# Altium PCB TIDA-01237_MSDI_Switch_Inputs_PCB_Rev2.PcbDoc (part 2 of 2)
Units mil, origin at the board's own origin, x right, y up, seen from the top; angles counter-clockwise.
Board outline 3000 x 5250 mil, 2 copper layers (Top Layer, Bottom Layer), stack 62 mil thick; 161 components, 119 nets, 511 pads, 360 vias.
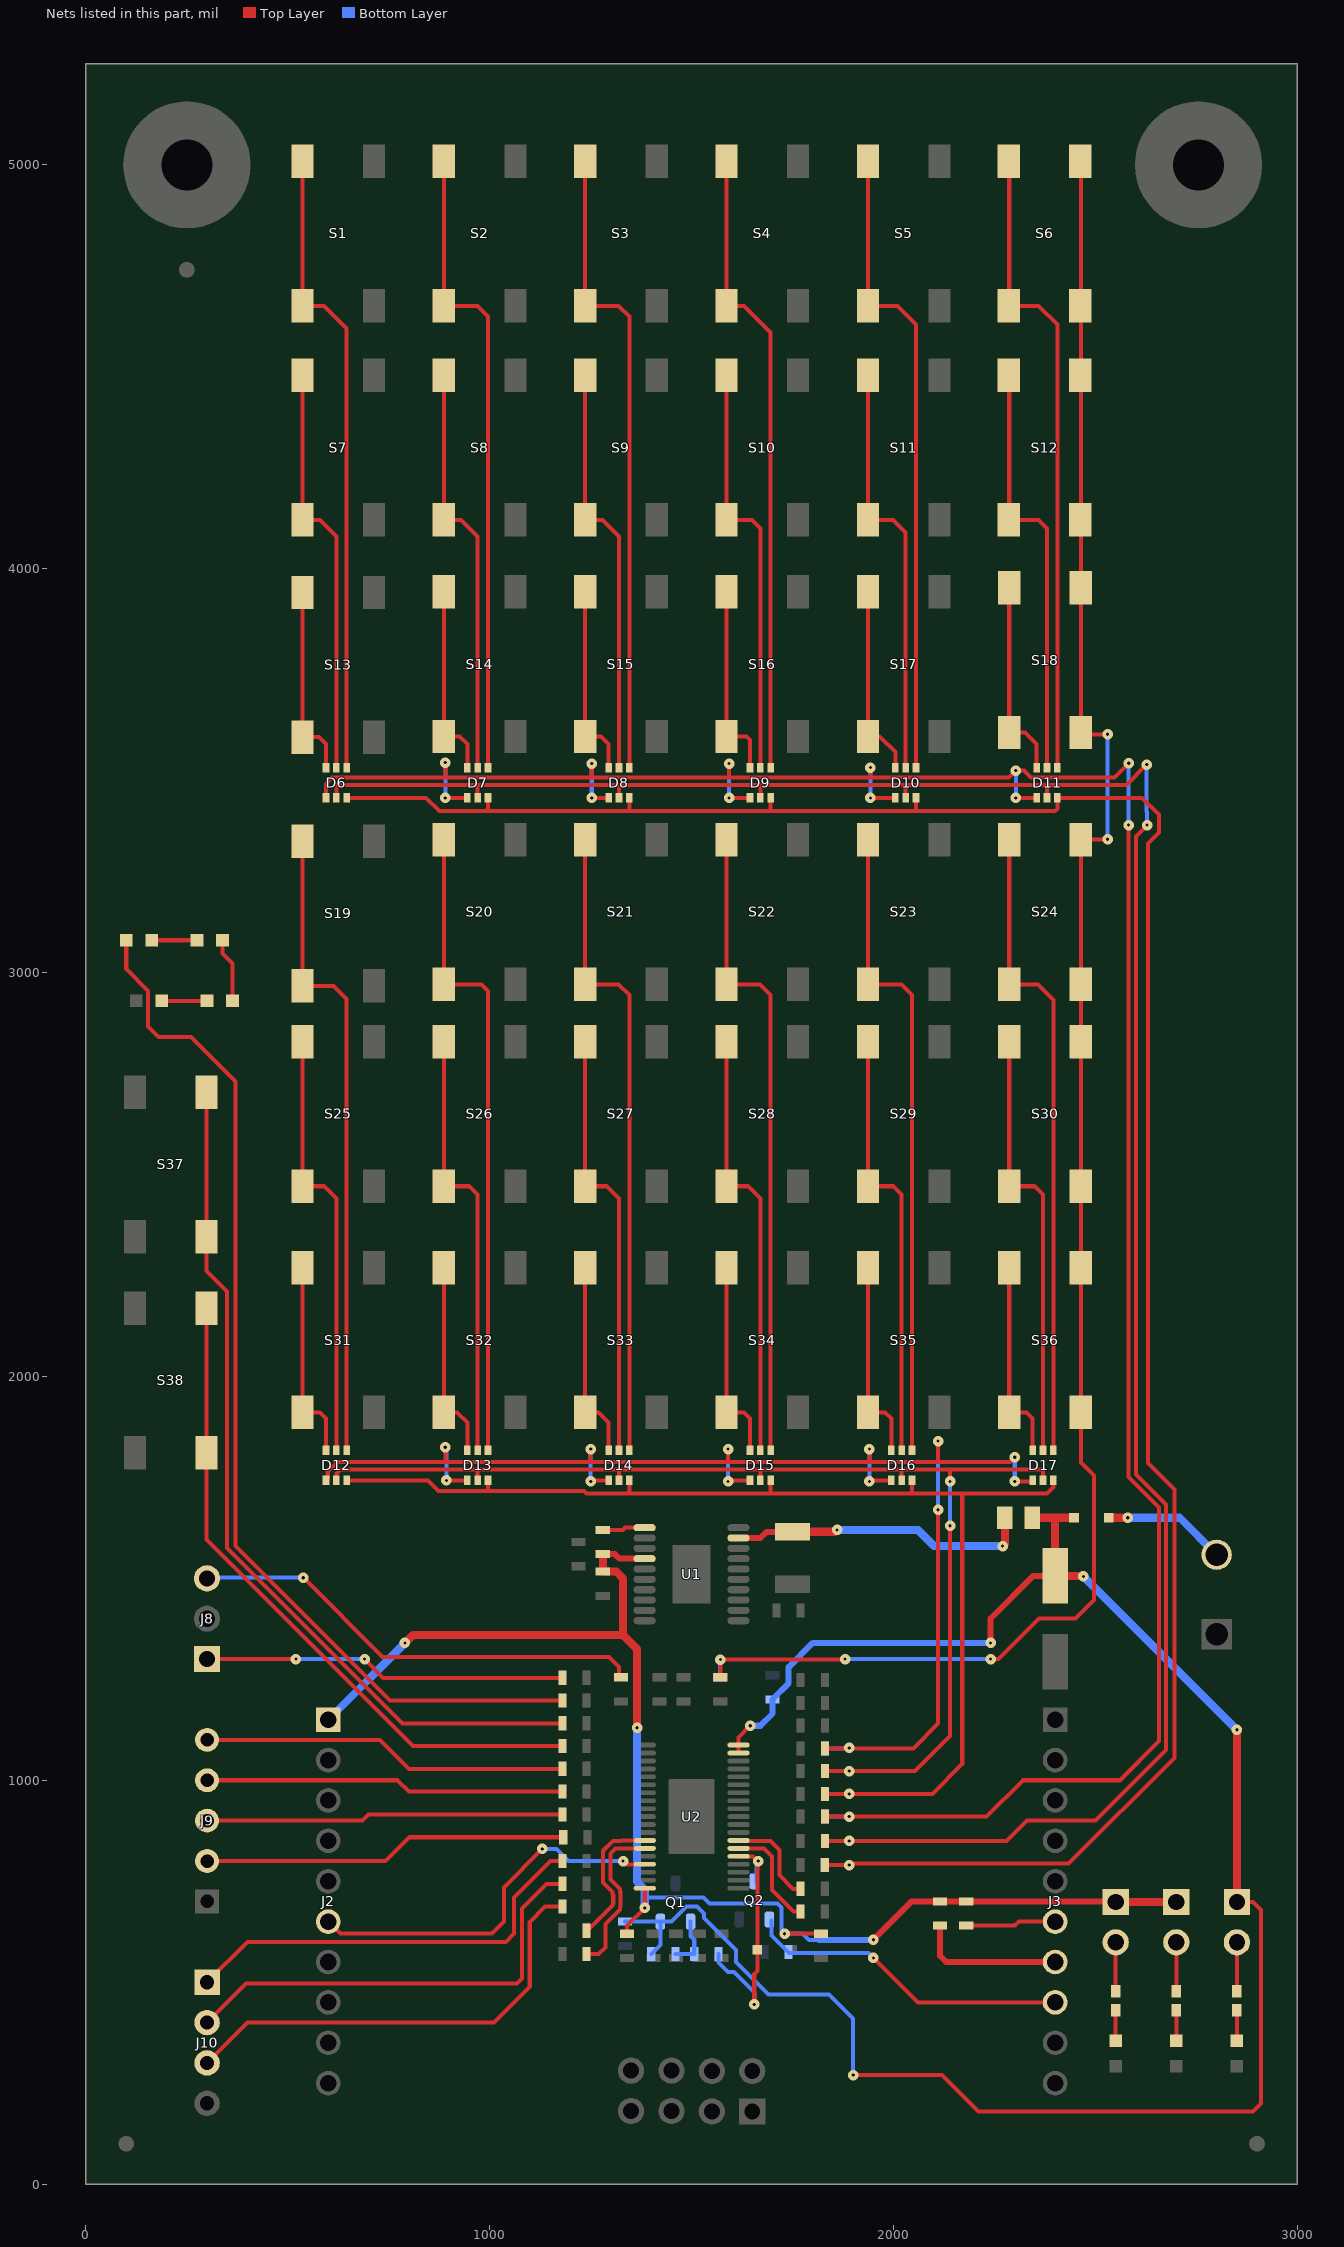
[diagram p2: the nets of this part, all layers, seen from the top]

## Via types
v1: diameter 20, hole 10, Top Layer to Bottom Layer, tented both sides, 214 vias
v2: diameter 26, hole 7.87, Top Layer to Bottom Layer, tented both sides, 116 vias
v3: diameter 19.68, hole 7.87, Top Layer to Bottom Layer, tented both sides, 18 vias
v4: diameter 26, hole 7.87, Top Layer to Bottom Layer, 12 vias

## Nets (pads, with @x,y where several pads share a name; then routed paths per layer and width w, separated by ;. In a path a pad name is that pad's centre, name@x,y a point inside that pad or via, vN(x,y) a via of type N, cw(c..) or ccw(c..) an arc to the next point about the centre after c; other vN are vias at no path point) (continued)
NetC21_1: C21.1 R22.1 S6.1 S6.2 S12.1 S12.2 S18.1 S18.2 S24.1 S24.2 S30.1 S30.2 S36.1 S36.2 | length 4778.2
  Top Layer w10: R22.1@1571.23,1255 v2(1571.23,1298.77) 1878.77,1298.77 v2(1880,1300) ; v2(2240,1300) 2260,1300 2360,1400 2450,1400 2495.87,1445.87 2495.87,1754.13 2463.58,1786.42 S36.2@2463.58,1910.87 S36.1@2463.58,2269.13 S30.2@2463.58,2470.87 S30.1@2463.58,2829.13 S24.2@2463.58,2970.87 S24.1@2463.58,3329.13 2529.13,3329.13 v2(2530,3330) ; S6.1@2463.58,5009.13 2463.58,4650.87 2463.58,4479.13 2463.58,4120.87 S18.1@2463.58,3952.8 S18.2@2463.58,3594.53 2468.11,3590 v2(2530,3590)
  Bottom Layer w10: C21.1@1570,1255 v2@1570,1297.54 ; v2(1880,1300) v2(2240,1300) ; v2(2530,3330) v2(2530,3590)
NetD2_2: D2.2 R3.1 | length 75.2
  Top Layer w10: D2.2@2550,354.96 R3.1@2550,430.18
NetD3_2: D3.2 R4.1 | length 75.2
  Top Layer w10: D3.2@2700,354.96 R4.1@2700,430.18
NetD4_2: D4.2 R5.1 | length 75.2
  Top Layer w10: D4.2@2850,354.96 R5.1@2850,430.18
NetD5_1: D5.1 Q2.3 R12.2 U2.24 | length 639.6
  Top Layer w10: U2.24@1616.14,811.58 1651.97,811.58 1662.47,801.07 D5.1@1662.47,580 1662.47,527.53 1655,520.05 v2(1655,445) ; v4@1663.54,800 v4(1665,800)
  Bottom Layer w10: R12.2@1566.45,570 1566.45,548.55 1590,525 1605,525 1655,475 v2(1655,445) ; Q2.3@1660,747.24 1660,798.59 1662.47,801.07 1663.54,800 v4(1665,800)
NetD6_1: D6.1 S1.3 S1.4 | length 1577.8
  Top Layer w10: S1.3@536.42,5009.13 S1.4@536.42,4650.87 589.13,4650.87 645.59,4594.41 D6.1@645.59,3507.4
NetD6_2: D6.2 S7.3 S7.4 | length 1031.4
  Top Layer w10: S7.3@536.42,4479.13 S7.4@536.42,4120.87 579.13,4120.87 620,4080 D6.2@620,3507.4
NetD6_3: D6.3 S13.3 S13.4 | length 481.6
  Top Layer w10: S13.3@536.42,3941.02 S13.4@536.42,3582.76 577.24,3582.76 594.41,3565.59 D6.3@594.41,3507.4
NetD7_1: D7.1 S2.3 S2.4 | length 1595.4
  Top Layer w10: S2.3@886.42,5009.13 S2.4@886.42,4650.87 969.13,4650.87 995.59,4624.41 D7.1@995.59,3507.4
NetD7_2: D7.2 S8.3 S8.4 | length 1031.4
  Top Layer w10: S8.3@886.42,4479.13 S8.4@886.42,4120.87 929.13,4120.87 970,4080 D7.2@970,3507.4
NetD7_3: D7.3 S14.3 S14.4 | length 482.3
  Top Layer w10: S14.3@886.42,3942.8 S14.4@886.42,3584.53 925.47,3584.53 944.41,3565.59 D7.3@944.41,3507.4
NetD8_1: D8.1 S3.3 S3.4 | length 1595.4
  Top Layer w10: S3.3@1236.42,5009.13 S3.4@1236.42,4650.87 1319.13,4650.87 1345.59,4624.41 D8.1@1345.59,3507.4
NetD8_2: D8.2 S9.3 S9.4 | length 1031.4
  Top Layer w10: S9.3@1236.42,4479.13 S9.4@1236.42,4120.87 1279.13,4120.87 1320,4080 D8.2@1320,3507.4
NetD8_3: D8.3 S15.3 S15.4 | length 482.3
  Top Layer w10: S15.3@1236.42,3942.8 S15.4@1236.42,3584.53 1275.47,3584.53 1294.41,3565.59 D8.3@1294.41,3507.4
NetD9_1: D9.1 S4.3 S4.4 | length 1572
  Top Layer w10: S4.3@1586.42,5009.13 S4.4@1586.42,4650.87 1629.13,4650.87 1695.59,4584.41 D9.1@1695.59,3507.4
NetD9_2: D9.2 S10.3 S10.4 | length 1043.1
  Top Layer w10: S10.3@1586.42,4479.13 S10.4@1586.42,4120.87 1649.13,4120.87 1670,4100 D9.2@1670,3507.4
NetD9_3: D9.3 S16.3 S16.4 | length 488.2
  Top Layer w10: S16.3@1586.42,3942.8 S16.4@1586.42,3584.53 1635.47,3584.53 1644.41,3575.59 D9.3@1644.41,3507.4
NetD10_1: D10.1 S5.3 S5.4 | length 1593.7
  Top Layer w10: S5.3@1936.42,5009.13 S5.4@1936.42,4650.87 2009.13,4650.87 2055.59,4604.41 D10.1@2055.59,3507.4
NetD10_2: D10.2 S11.3 S11.4 | length 1047.2
  Top Layer w10: S11.3@1936.42,4479.13 S11.4@1936.42,4120.87 1999.13,4120.87 2030,4090 D10.2@2030,3507.4
NetD10_3: D10.3 S17.3 S17.4 | length 480.6
  Top Layer w10: S17.3@1936.42,3942.8 S17.4@1936.42,3584.53 1965.47,3584.53 2004.41,3545.59 D10.3@2004.41,3507.4
NetD11_1: D11.1 S6.3 S6.4 | length 1593.7
  Top Layer w10: S6.3@2286.42,5009.13 2286.42,4650.87 2359.13,4650.87 2405.59,4604.41 D11.1@2405.59,3507.4
NetD11_2: D11.2 S12.3 S12.4 | length 1053.1
  Top Layer w10: S12.3@2286.42,4479.13 2286.42,4120.87 2359.13,4120.87 2380,4100 D11.2@2380,3507.4
NetD11_3: D11.3 S18.3 S18.4 | length 496.4
  Top Layer w10: S18.3@2286.42,3952.8 S18.4@2286.42,3594.53 2325.47,3594.53 2354.41,3565.59 D11.3@2354.41,3507.4
NetD12_1: D12.1 S19.3 S19.4 | length 1598
  Top Layer w10: S19.3@536.42,3325.47 S19.4@536.42,2967.2 612.8,2967.2 645.59,2934.41 D12.1@645.59,1817.4
NetD12_2: D12.2 S25.3 S25.4 | length 1077.2
  Top Layer w10: S25.3@536.42,2829.13 S25.4@536.42,2470.87 589.13,2470.87 620,2440 D12.2@620,1817.4
NetD12_3: D12.3 S31.3 S31.4 | length 500.8
  Top Layer w10: S31.3@536.42,2269.13 S31.4@536.42,1910.87 579.13,1910.87 594.41,1895.59 D12.3@594.41,1817.4
NetD13_1: D13.1 S20.3 S20.4 | length 1611.3
  Top Layer w10: S20.3@886.42,3329.13 S20.4@886.42,2970.87 979.13,2970.87 995.59,2954.41 D13.1@995.59,1817.4
NetD13_2: D13.2 S26.3 S26.4 | length 1083.1
  Top Layer w10: S26.3@886.42,2829.13 S26.4@886.42,2470.87 949.13,2470.87 970,2450 D13.2@970,1817.4
NetD13_3: D13.3 S32.3 S32.4 | length 494.9
  Top Layer w10: S32.3@886.42,2269.13 S32.4@886.42,1910.87 919.13,1910.87 944.41,1885.59 D13.3@944.41,1817.4
NetD14_1: D14.1 S21.3 S21.4 | length 1605.4
  Top Layer w10: S21.3@1236.42,3329.13 S21.4@1236.42,2970.87 1319.13,2970.87 1345.59,2944.41 D14.1@1345.59,1817.4
NetD14_2: D14.2 S27.3 S27.4 | length 1077.2
  Top Layer w10: S27.3@1236.42,2829.13 S27.4@1236.42,2470.87 1289.13,2470.87 1320,2440 D14.2@1320,1817.4
NetD14_3: D14.3 S33.3 S33.4 | length 494.9
  Top Layer w10: S33.3@1236.42,2269.13 S33.4@1236.42,1910.87 1269.13,1910.87 1294.41,1885.59 D14.3@1294.41,1817.4
NetD15_1: D15.1 S22.3 S22.4 | length 1605.4
  Top Layer w10: S22.3@1586.42,3329.13 S22.4@1586.42,2970.87 1669.13,2970.87 1695.59,2944.41 D15.1@1695.59,1817.4
NetD15_2: D15.2 S28.3 S28.4 | length 1077.2
  Top Layer w10: S28.3@1586.42,2829.13 S28.4@1586.42,2470.87 1639.13,2470.87 1670,2440 D15.2@1670,1817.4
NetD15_3: D15.3 S34.3 S34.4 | length 500.8
  Top Layer w10: S34.3@1586.42,2269.13 S34.4@1586.42,1910.87 1629.13,1910.87 1644.41,1895.59 D15.3@1644.41,1817.4
NetD16_1: D16.1 S23.3 S23.4 | length 1605.4
  Top Layer w10: S23.3@1936.42,3329.13 S23.4@1936.42,2970.87 2019.13,2970.87 2045.59,2944.41 D16.1@2045.59,1817.4
NetD16_2: D16.2 S29.3 S29.4 | length 1083.1
  Top Layer w10: S29.3@1936.42,2829.13 S29.4@1936.42,2470.87 1999.13,2470.87 2020,2450 D16.2@2020,1817.4
NetD16_3: D16.3 S35.3 S35.4 | length 500.8
  Top Layer w10: S35.3@1936.42,2269.13 S35.4@1936.42,1910.87 1979.13,1910.87 1994.41,1895.59 D16.3@1994.41,1817.4
NetD17_1: D17.1 S24.3 S24.4 | length 1598.5
  Top Layer w10: S24.3@2286.42,3329.13 S24.4@2286.42,2970.87 2357.3,2970.87 2395.59,2932.57 D17.1@2395.59,1817.4
NetD17_2: D17.2 S30.3 S30.4 | length 1083.1
  Top Layer w10: S30.3@2286.42,2829.13 S30.4@2286.42,2470.87 2349.13,2470.87 2370,2450 D17.2@2370,1817.4
NetD17_3: D17.3 S36.3 S36.4 | length 500.8
  Top Layer w10: S36.3@2286.42,2269.13 S36.4@2286.42,1910.87 2329.13,1910.87 2344.41,1895.59 D17.3@2344.41,1817.4
NetD18_1: D18.1 D19.2 | length 112
  Top Layer w10: D18.1@163.03,3080 D19.2@275.04,3080
NetD18_2: D18.2 R32.1 | length 2627.2
  Top Layer w10: D18.2@100.04,3080 D18.2@100.04,3080 100,3008.4 153.66,2954.74 153.66,2866.34 180,2840 260,2840 370,2730 370,1580 752.62,1197.38 R32.1@1180,1197.38
NetD19_1: D19.1 D20.2 | length 160.4
  Top Layer w10: D19.1@338.03,3080 338.03,3047.13 363.03,3022.13 D20.2@363.03,2930
NetD20_1: D20.1 D21.2 | length 112
  Top Layer w10: D21.2@188.03,2930 D20.1@300.04,2930
NetJ4_2: J4.2 R3.2 | length 121.4
  Top Layer w10: R3.2@2550,477.42 J4.2@2550,598.81
NetJ5_2: J5.2 R4.2 | length 121.4
  Top Layer w10: R4.2@2700,477.42 J5.2@2700,598.81
NetJ6_2: J6.2 R5.2 | length 121.4
  Top Layer w10: R5.2@2850,477.42 J6.2@2850,598.81
NetJ8_1: J8.1 R29.1 | length 899.2
  Top Layer w10: J8.1@300,1300 v2(520,1300) ; v2(690,1300) 736.31,1253.69 R29.1@1180,1253.69
  Bottom Layer w10: v2(520,1300) v2(690,1300)
NetJ8_3: J8.3 R28.1 | length 1137.4
  Top Layer w10: v2(538.42,1501.58) 735,1305 1295,1305 1320,1280 R28.1@1320,1255
  Bottom Layer w10: J8.3@300,1500 301.58,1501.58 v2(538.42,1501.58)
NetJ9_2: J9.2 R36.1 | length 906.4
  Top Layer w10: J9.2@300,800 742.15,800 801.07,858.93 R36.1@1181.95,858.93
NetJ9_3: J9.3 R35.1 | length 886.3
  Top Layer w10: J9.3@300,900 685,900 700.24,915.24 R35.1@1180,915.24
NetJ9_4: J9.4 R34.1 | length 891.5
  Top Layer w10: J9.4@300,1000 772.15,1000 800,972.15 R34.1@1180,972.15
NetJ9_5: J9.5 R33.1 | length 909.6
  Top Layer w10: J9.5@300,1100 728.46,1100 800,1028.46 R33.1@1180,1028.46
NetJ10_1: J10.1 R39.1 | length 1057
  Top Layer w10: J10.1@300,500 400,600 1040,600 1060,620 1060,710 1150,800 R39.1@1180,800
NetJ10_2: J10.2 R38.1 | length 1124
  Top Layer w10: J10.2@300,400 397.06,497.06 1067.78,497.06 1080,509.28 1080,682.8 1140.89,743.69 R38.1@1180,743.69
NetJ10_3: J10.3 R37.1 | length 1134.2
  Top Layer w10: J10.3@300,300 400,400 1010,400 1099.13,489.13 1099.13,649.13 1137.38,687.38 R37.1@1180,687.38
NetQ1_1: Q1.1 R10.1 R12.1 | length 130.4
  Bottom Layer w10: R10.1@1460,570 R12.1@1506.45,570 1506.45,604.72 1497.4,613.77 Q1.1@1497.4,650.21
NetR2_1: R2.1 U1.1 | length 105.8
  Top Layer w10: R2.1@1280,1620 1330,1620 1335.47,1625.47 U1.1@1383.54,1625.47
NetR8_2: R8.2 U2.13 | length 350.4
  Top Layer w10: R8.2@1240,627.38 1241.63,627.38 1304.25,690 1304.25,692.66 1305.87,694.28 1305.87,715.72 1304.25,717.34 1304.25,723.88 1280.75,747.38 1280.75,825.47 1305.28,850 1325.97,850 1326.91,850.95 U2.13@1383.86,850.95
NetR9_2: R9.2 U2.14 | length 401.6
  Top Layer w10: R9.2@1240,569.69 1269.69,569.69 1286.25,586.25 1286.25,644.13 1322.13,680 1322.13,682.6 1322.13,685.26 1323.75,686.88 1323.75,723.12 1322.13,724.74 1322.13,731.28 1298.62,754.79 1298.62,818.07 1311.82,831.26 U2.14@1383.86,831.26
NetR11_2: R11.2 U2.25 | length 266.8
  Top Layer w10: U2.25@1616.14,831.26 1678.74,831.26 1699.25,810.75 1699.25,728.42 1752.68,674.99 R11.2@1770,674.99
NetR14_2: R14.2 U2.26 | length 239.9
  Top Layer w10: U2.26@1616.14,850.95 1617.05,850.04 1694.96,850.04 1717.13,827.87 1717.13,765.6 1751.42,731.3 R14.2@1770,731.3
NetR30_1: R30.1 S37.1 S37.2 | length 2160.2
  Top Layer w10: S37.1@298.58,2704.03 S37.2@298.58,2345.76 298.58,2261.42 350,2210 350,1574.72 745.21,1179.51 745.49,1179.51 783.93,1141.07 1178.5,1141.07 R30.1@1180,1141.07
NetR31_1: R31.1 S38.1 S38.2 | length 1666.1
  Top Layer w10: S38.1@298.58,2169.13 S38.2@298.58,1810.87 298.58,1596.42 810.24,1084.76 1178.5,1084.76 R31.1@1180,1084.76
P1_6: J3.7 R41.1 | length 364.7
  Top Layer w15: R41.1@2115,638.5 2115,565 2130,550 J3.7@2400,550
P1_7: J3.6 R40.1 | length 224.1
  Top Layer w10: R40.1@2180,640 2300,640 2310,650 J3.6@2400,650
R1: C15.1 D6.6 D7.6 D8.6 D9.6 D10.6 D11.6 R16.1 | length 5619.5
  Top Layer w10: D6.6@645.59,3432.6 842.4,3432.6 875,3400 990,3400 ; D7.6@995.59,3432.6 995.59,3405.59 990,3400 ; D8.6@1345.59,3432.6 1345.59,3405.59 1340,3400 ; D9.6@1695.59,3432.6 1695.59,3405.59 1690,3400 ; R16.1@1830,790 v2(1890,790) 1893.39,793.39 2433.39,793.39 2695,1055 2695,1720 2630,1785 2630,3320 2656.67,3346.67 2656.67,3390.92 2615,3432.6 D11.6@2405.59,3432.6 2405.59,3405.59 2400,3400 2050,3400 ; D10.6@2055.59,3432.6 2055.59,3405.59 2050,3400 ; 990,3400 1340,3400 ; 1340,3400 1690,3400 ; 1690,3400 2050,3400
  Bottom Layer w10: C15.1@1830,790 v2(1890,790)
R2: C22.1 D6.5 D7.5 D8.5 D9.5 D10.5 D11.5 R23.1 | length 5701.4
  Top Layer w10: D6.5@620,3432.6 620,3460 624.84,3464.84 970,3464.84 ; D7.5@970,3432.6 970,3464.84 ; D8.5@1320,3432.6 1320,3464.84 ; D9.5@1670,3432.6 1670,3464.84 ; R23.1@1830,850 2280,850 2330,900 2500,900 2675,1075 2675,1682.4 2600,1757.4 2600,3336.59 2627.85,3364.43 v4(2627.85,3365) ; D10.5@2030,3432.6 2030,3464.84 ; D11.5@2380,3432.6 2380,3460 2375.16,3464.84 ; v4(2626.72,3515) 2576.56,3464.84 2375.16,3464.84 ; 970,3464.84 1320,3464.84 ; 1320,3464.84 1670,3464.84 ; 1670,3464.84 2030,3464.84 ; 2030,3464.84 2375.16,3464.84
  Bottom Layer w10: C22.1@1830,850 v2(1890,850) ; v4(2626.72,3515) 2626.72,3398.28 2627.85,3397.15 v4(2627.85,3365)
R3: C23.1 D6.4 D7.4 D8.4 D9.4 D10.4 D11.4 R24.1 | length 6270.3
  Top Layer w10: D6.4@594.41,3432.6 594.41,3467.13 610,3482.72 890,3482.72 ; v2(890,3432.6) D7.4@944.41,3432.6 ; v2(890,3520) 890,3482.72 ; v2(1252.6,3432.6) D8.4@1294.41,3432.6 ; v2(1252.6,3517.4) 1252.6,3485.31 1250,3482.72 ; v2(1592.6,3432.6) D9.4@1644.41,3432.6 ; v2(1592.6,3517.4) 1592.6,3485.31 1590,3482.72 ; R24.1@1830,910 2230,910 2320,1000 2560,1000 2657.13,1097.13 2657.13,1675 2581.72,1750.41 v4(2581.72,3365) ; v2(1942.6,3432.6) D10.4@2004.41,3432.6 ; v2(1942.6,3507.4) 1942.6,3485.31 1940,3482.72 ; v2(2302.6,3432.6) D11.4@2354.41,3432.6 ; v4(2582.13,3518.18) 2546.67,3482.72 2340.81,3482.72 2323.53,3500 v2(2302.6,3500) 2285.32,3482.72 1940,3482.72 ; 890,3482.72 1250,3482.72 ; 1250,3482.72 1590,3482.72 ; 1590,3482.72 1940,3482.72
  Bottom Layer w10: v2(890,3432.6) v2(890,3520) ; v2(1252.6,3432.6) v2(1252.6,3517.4) ; v2(1592.6,3432.6) v2(1592.6,3517.4) ; C23.1@1830,910 v2(1890,910) ; v2(1942.6,3432.6) v2(1942.6,3507.4) ; v2(2302.6,3432.6) v2(2302.6,3500) ; v4(2581.72,3365) 2581.72,3481.72 2582.13,3482.13 v4(2582.13,3518.18)
R4: C24.1 D12.6 D13.6 D14.6 D15.6 D16.6 D17.6 R25.1 | length 3044
  Top Layer w10: D12.6@645.59,1742.6 847.4,1742.6 873.28,1716.72 995.59,1716.72 ; D13.6@995.59,1742.6 995.59,1716.72 ; D14.6@1345.59,1742.6 1345.59,1715.59 1340,1710 ; D15.6@1695.59,1738.19 1695.59,1710 ; D15.6@1695.59,1742.6 1695.59,1710 ; R25.1@1830,966.31 v2(1890,966.31) 2096.31,966.31 2170,1040 2170,1710 ; D16.6@2045.59,1742.6 2045.59,1715.59 2040,1710 ; D17.6@2395.59,1742.6 2395.59,1725.59 2380,1710 2170,1710 ; 995.59,1716.72 1233.28,1716.72 1240,1710 1340,1710 ; 1340,1710 1695.59,1710 ; 1695.59,1710 2040,1710 ; 2040,1710 2170,1710
  Bottom Layer w10: C24.1@1830,966.31 v2(1890,966.31)
R5: C25.1 D12.5 D13.5 D14.5 D15.5 D16.5 D17.5 R26.1 | length 2972.9
  Top Layer w10: D12.5@620,1742.6 620,1760 630,1770 970,1770 ; D13.5@970,1742.6 970,1770 ; D14.5@1320,1742.6 1320,1770 ; D15.5@1670,1742.6 1670,1770 ; R26.1@1830,1022.62 v2(1890,1022.62) 2052.62,1022.62 2140,1110 v2(2140,1630) ; D16.5@2020,1742.6 2020,1767.5 2017.5,1770 ; v2(2140,1740) 2140,1770 ; D17.5@2370,1742.6 2370,1765 2365,1770 2140,1770 ; 970,1770 1320,1770 ; 1320,1770 1670,1770 ; 1670,1770 2017.5,1770 ; 2017.5,1770 2140,1770
  Bottom Layer w10: C25.1@1830,1022.62 v2(1890,1022.62) ; v2(2140,1630) v2(2140,1740)
R6: C26.1 D12.4 D13.4 D14.4 D15.4 D16.4 D17.4 R27.1 | length 3629.1
  Top Layer w10: D12.4@594.41,1742.6 598.86,1747.05 598.86,1764.14 622.6,1787.87 890,1787.87 ; v2(890,1824.8) 890,1787.87 ; v2(892.6,1742.6) D13.4@944.41,1742.6 ; v2(1250,1740) 1252.6,1742.6 D14.4@1294.41,1742.6 ; v2(1250,1820) 1250,1787.87 ; v2(1590,1740) 1592.6,1742.6 D15.4@1644.41,1742.6 ; v2(1590,1820) 1590,1787.87 ; R27.1@1830,1078.93 2048.93,1078.93 2110,1140 v2(2110,1670) ; v2(1940,1740) 1942.6,1742.6 D16.4@1994.41,1742.6 ; v2(1940,1820) 1940,1787.87 ; v2(2110,1840) 2110,1787.87 ; v2(2300,1740) D17.4@2341.81,1740 ; v2(2300,1800) 2287.87,1787.87 2110,1787.87 ; 890,1787.87 1250,1787.87 ; 1250,1787.87 1590,1787.87 ; 1590,1787.87 1940,1787.87 ; 1940,1787.87 2110,1787.87
  Bottom Layer w10: v2(890,1824.8) 892.6,1827.4 v2(892.6,1742.6) ; v2(1250,1740) v2(1250,1820) ; v2(1590,1740) v2(1590,1820) ; C26.1@1830,1078.93 1888.93,1078.93 v2(1890,1080) ; v2(1940,1740) v2(1940,1820) ; v2(2110,1670) v2(2110,1840) ; v2(2300,1740) v2(2300,1800)
SCLK: J2.6 U2.16 | length 937.4
  Top Layer w10: J2.6@600,650 630,620 1005,620 1035,650 1035,735 v2(1130,830) ; v2@1338.11,791.89 U2.16@1383.86,791.89
  Bottom Layer w10: v2(1130,830) 1165.17,830 1195.17,800 v2(1330,800)
UC_LDO_EN: J3.8 Q2.1 R15.1 | length 808.1
  Top Layer w10: v2(1950,560) 2060,450 J3.8@2400,450
  Bottom Layer w10: Q2.1@1697.4,652.76 1697.4,616.01 1741.25,572.16 1750,572.16 1937.84,572.16 v2(1950,560)
V3P3: C1.1 C9.1 J2.1 J4.1 J5.1 R2.2 R13.2 R40.2 R41.2 U1.4 U2.19 | length 3518
  Top Layer w10: C9.1@1340,620 1340,640 v2(1383.86,683.86) U2.19@1383.86,732.84 ; v2(1730,620) R13.2@1820,620
  Top Layer w15: R2.2@1280,1560 1310,1560 1321.3,1548.7 U1.4@1383.54,1548.7 ; v2(1950,605) 2045,700 R41.2@2115,700 R40.2@2180,700 2548.81,700 J4.1@2550,698.81
  Top Layer w20: v2(790,1340) 810,1360 1330,1360 ; R2.2@1280,1560 C1.1@1280,1516.45 1313.55,1516.45 1330,1500 1330,1360 ; v2(1365,1130) 1365,1325 1330,1360 ; J4.1@2550,698.81 J5.1@2700,698.81
  Bottom Layer w10: 1383.86,710 1528.9,710 1543.9,695 1712.1,695 1722.09,685.02 1722.09,627.91 v2(1730,620) 1775,620 1790,605 1815,605
  Bottom Layer w15: 1815,605 v2(1950,605)
  Bottom Layer w20: J2.1@600,1150 v2(790,1340) ; v2(1365,1130) 1365,748.86 1383.86,730 1383.86,710 v2(1383.86,683.86)
VBATT: D1.2 J1.2 | length 304.6
  Top Layer w20: D1.2@2533.31,1650 v4(2580,1650)
  Bottom Layer w20: v4(2580,1650) 2708.43,1650 J1.2@2800,1558.43
VIN: C3.1 R1.2 U1.19 | length 751.3
  Top Layer w15: U1.19@1615.83,1599.88 1670,1599.88 1685.39,1615.27 C3.1@1750,1615.27
  Top Layer w20: C3.1@1750,1615.27 1855.27,1615.27 v2(1860,1620) ; v2(2270,1580) 2275.35,1585.35 R1.2@2275.35,1650
  Bottom Layer w20: v2(1860,1620) 2060,1620 2100,1580 v2(2270,1580)
VSUP: C2.1 C6.1 C8.1 D1.1 J6.1 Q1.2 R1.1 R10.2 U2.37 U2.38 | length 4900.3
  Top Layer w10: U2.37@1616.14,1067.48 U2.38@1616.14,1087.17 1616.14,1106.14 v2(1645,1135) ; v2(1900,270) 2120,270 2210,180 2890,180 2910,200 2910,678.81 2890,698.81 J6.1@2850,698.81
  Top Layer w15: v2(2240,1340) 2240,1400 2346.3,1506.3 C2.1@2400,1506.3
  Top Layer w20: R1.1@2343.46,1650 2400,1650 ; D1.1@2446.69,1650 2400,1650 ; v2(2470,1504.87) 2468.57,1506.3 C2.1@2400,1506.3 2400,1650 ; J6.1@2850,698.81 v4(2850,1124.87)
  Bottom Layer w10: C6.1@1335.21,650.21 Q1.2@1422.6,650.21 ; R10.2@1400,570 1422.6,592.6 Q1.2@1422.6,650.21 ; v2(1900,270) 1900,410 1840,470 1690,470 1610,550 1610,580 1530.92,659.08 1530.92,670 1513.16,687.77 1487.77,687.77 1450.21,650.21 Q1.2@1422.6,650.21
  Bottom Layer w15: v2(1645,1135) 1670,1135 1700.4,1165.4 1700.4,1199.6 C8.1@1700,1200 1740,1240 1740,1280 1800,1340 v2(2240,1340)
  Bottom Layer w20: v2(2470,1504.87) v4(2850,1124.87)
pads on no net: FID1.1 FID2.1 FID3.1 H1.1 H2.1 J2.2 J2.5 J2.8 J2.9 J2.10 J3.2 J3.3 J3.4 J3.5 U1.2 U1.5 U1.6 U1.16 U1.17 U1.18 U1.20

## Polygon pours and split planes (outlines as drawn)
GND on Bottom Layer "BOTTOM_LAYER_GND_P000" (solid, pour order 0): -2.02,5255.08 2997.98,5255.08 2997.98,5.08 -2.02,5.08
GND on Top Layer "TOP_LAYER_GND_P004" (solid, remove dead copper, pour order 4): 0,0 3000,0 3000,5250 0,5250 0,0
GND on Top Layer "TOP_LAYER_GND_P002" (solid, remove dead copper, pour order 2): 1340,1380.39 1340,1502.34 1413.07,1502.34 1413.07,1605 1600,1605 1600,1497.52 1649.51,1497.52 1649.51,1380.39

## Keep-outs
Keep-Out Layer:
  text ".Layer_Name" at 577,-858.49 h60

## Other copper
Top Layer:
  text ".Layer_Name" at 577,-858.49 h60
Bottom Layer:
  rectangle net GND: 1440,1435 1560,1595
  rectangle net GND: 1420,815 1588.58,1020
  text ".Layer_Name" at 577,-858.49 h60

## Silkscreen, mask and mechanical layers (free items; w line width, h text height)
Top Overlay:
  region: 2725,3245 2725,2945 2825,2945 2825,3245
  lines w7: 55,2755 365,2755 ; 56.54,3190 396.54,3190 ; 990,265 990,320 1245,320 1245,265 ; 1115,335 1115,350 1500,350 1500,340 ; 2480,820 2960,820 ; 450,5150 450,5230 2550,5230 2550,5150 ; 450,5150 450,1710 2550,1710 2550,5150 ; 450,5150 2550,5150 ; 1160,1280 1160,1340 1850,1340 1850,1280 ; 1160,1280 1160,540 1850,540 1850,1280 ; 1160,1280 1850,1280 ; 55,1740 365,1740 365,2825 55,2825 55,1740 ; 56.54,2870 56.54,3260 396.54,3260 396.54,2870 56.54,2870 ; 2480,190 2480,900 2960,900 2960,190 2480,190
  text "Matrix Configuration Switch Inputs: 6 x 6" at 890,5175 h70
  text "IN17" at 180,3280 h63
  text "LED Backlighting" at 76.54,3210 h45
  text "Multi-Switch" at 100,2775 h45
  text "IN18" at 160,2230 h63
  text "TIDA-01237 Rev 2" at 2810,2080 h108.27 r90
  text "VBATT" at 2720,1695 h63
  text "Rocker / Switch" at 18.09,1320 h63
  text "MSDI Size 17.5 x 18.8 mm" at 1260,1295 h50
  text "IN16 /  / GND /  / IN16" at 385,1275 h63
  text "J2" at 585,1195 h63
  text "GND" at 2740,1190 h63
  text "J3" at 2470,1095 h63
  text "LED Indicators" at 2550,840 h60
  text "Light / Control / Arm" at 14.58,790 h63
  text "IN19 /  / IN20 /  / IN21 /  / IN22 /  / GND" at 385,645 h63
  text "Wiper / Control / Arm" at 25.49,236.25 h63
  text "V3P3 /  / NC /  / MISO /  / MOSI /  / NC /  / SCLK /  / nCS /  / NC /  / NC /  / NC" at 665,215 h63
  text "GND /  / NC /  / NC /  / NC /  / NC /  / P1.7 /  / P1.6 /  / uC_LDO_EN /  / MSDI_INT /  / MSDI_RST" at 1965,200 h63
  text "/INT" at 2510,199.94 h60
  text "V3P3" at 2640,200 h60
  text "VSUP" at 2785,200 h60
  text "IN23 /  / IN23 /  / IN23 /  / GND" at 390,155 h65
  text "GND IN0 / GND IN1 / GND IN2 / GND IN3" at 1235,85 h63 r90
  text ".Layer_Name" at 577,-858.49 h60
Bottom Overlay:
  lines w7: 1160.49,1282.62 1160.49,1342.62 1850.49,1342.62 1850.49,1282.62 ; 1160.49,1282.62 1850.49,1282.62 ; 1160.49,1282.62 1160.49,542.62 1850.49,542.62 1850.49,1282.62
  text "MSDI Size 17.5 x 18.8 mm" at 1750.49,1297.62 h50
  text "V3P3 /  / NC /  / MISO /  / MOSI /  / NC /  / SCLK /  / nCS /  / NC /  / NC /  / NC" at 1025,215 h63
  text "GND /  / NC /  / NC /  / NC /  / NC /  / P1.7 /  / P1.6 /  / uC_LDO_EN /  / MSDI_INT /  / MSDI_RESET" at 2330,200 h63
  text ".Layer_Name" at 577,-858.49 h60
Top Paste:
  text ".Layer_Name" at 577,-858.49 h60
Bottom Paste:
  text ".Layer_Name" at 577,-858.49 h60
Top Solder:
  text ".Layer_Name" at 577,-858.49 h60
  text ".Layer_Name" at 577,-858.49 h60
Bottom Solder:
  text ".Layer_Name" at 577,-858.49 h60
Drill Guide:
  text ".Layer_Name" at 577,-858.49 h60
M1 Board Outline:
  the board outline again, w10
  text ".Layer_Name" at 577,-858.49 h60
M2 Board Dimensions:
  rectangle: 0,-275 125,-150
  rectangle: 125,-400 500,-275
  lines w7: 0,-275 1000,-275 ; 125,-400 125,-150 ; 250,-400 250,-150 ; 500,-400 500,-150 ; 750,-400 750,-150 ; 0,-400 1000,-400 1000,-150 0,-150 0,-400
  text ".Layer_Name" at 577,-858.49 h60
M3 3D STEP Top:
  text ".Layer_Name" at 577,-858.49 h60
M4 3D STEP Bottom:
  text ".Layer_Name" at 577,-858.49 h60
M5 Assembly Top:
  lines w10: -292,-930.17 6308,-930.17 ; -292,-726.83 6310,-726.83 ; -292,-523.5 -292,-1133.5 3713,-1133.5 6310,-1133.5 6310,-523.5 -291.5,-523.5 -291.5,-1133.5 1284,-1133.5 ; 2173,-1133.5 2173,-523.5 ; 3440,-726.83 3440,-523.5 ; 4280,-726.83 4280,-523.5 ; 4902,-1140 4902,-937.17
  text "COMPONENTS MARKED 'DNP' SHOULD NOT BE POPULATED." at 1153.5,-318.5 h60
  text "ASSEMBLY VARIANT:" at 1153,-434 h60
  text ".VariantName" at 2189,-434 h60
  text "PCB VIEWED FROM TOP SIDE" at -228.5,-655.67 h60
  text "BOARD #:" at 2248,-655.67 h60
  text ".PRJ_Number" at 2793.5,-655.67 h60
  text "REV:" at 3638,-655.67 h60
  text ".PCB_Rev" at 3929.5,-655.67 h60
  text "SVN REV:" at 4476,-655.67 h60
  text ".VersionControl_RevNumber" at 4982,-655.67 h60
  text "TID #:" at 2248,-859 h60
  text ".TID" at 2793.5,-859 h60
  text "PLOT NAME =" at -228.5,-1064.34 h60
  text ".plot_File_Name" at 577,-1064.34 h60
  text "GENERATED    :" at 2250,-1064.34 h60
  text ".Print_Date" at 3119.5,-1064.34 h60
  text ".Print_Time" at 3848.5,-1064.34 h60
  text "TEXAS INSTRUMENTS" at 5113,-1064.34 h60
M6 Assembly Bottom:
  lines w10: -292.5,-727.33 6309.5,-727.33 ; -290.5,-930.67 6309.5,-930.67 ; 1115.5,-1140.5 1115.5,-937.67 ; 1737.5,-727.33 1737.5,-524 ; 2577.5,-727.33 2577.5,-524 ; 3844.5,-1134 3844.5,-524 ; 4733.5,-1134 6309,-1134 6309,-524 -292.5,-524 -292.5,-1134 2304.5,-1134 6309.5,-1134 6309.5,-524
  text "COMPONENTS MARKED 'DNP' SHOULD NOT BE POPULATED." at 6102,-318 h60
  text ".VariantName" at 5058,-434 h60
  text "ASSEMBLY VARIANT:" at 6097,-434 h60
  text ".VersionControl_RevNumber" at 1035.5,-656.17 h60
  text "SVN REV:" at 1541.5,-656.17 h60
  text ".PCB_Rev" at 2088,-656.17 h60
  text "REV:" at 2379.5,-656.17 h60
  text ".PRJ_Number" at 3224,-656.17 h60
  text "BOARD #:" at 3769.5,-656.17 h60
  text "PCB VIEWED FROM BOTTOM SIDE" at 6246,-656.17 h60
  text ".TID" at 3224,-859.5 h60
  text "TID #:" at 3769.5,-859.5 h60
  text "TEXAS INSTRUMENTS" at 904.5,-1064.84 h60
  text ".Print_Time" at 2169,-1064.84 h60
  text ".Print_Date" at 2898,-1064.84 h60
  text "GENERATED    :" at 3767.5,-1064.84 h60
  text ".plot_File_Name" at 5440.5,-1064.84 h60
  text "PLOT NAME =" at 6246,-1064.84 h60
M9 Title Sheet:
  drawing of 57 lines, arcs and shapes, not listed
  text "1" at 739.84,8036.5 h70
  text "2" at 3235.5,8036.5 h70
  text "3" at 5724.84,8036.5 h70
  text "4" at 8231.51,8036.5 h70
  text "5" at 10730.5,8036.5 h70
  text "6" at 13235.5,8036.5 h70
  text "A" at -416.5,6893.5 h70
  text "A" at 14383.5,6893.5 h70
  text "B" at -416.5,4513.5 h70
  text "B" at 14383.5,4513.5 h70
  text "C" at -416.5,2138.5 h70
  text "C" at 14383.5,2138.5 h70
  text "PROJECT TITLE:" at 11343.5,277.5 h45
  text ".PRJ_Title" at 11393.5,144.17 h70
  text "DESIGNED FOR:" at 11343.5,-23.5 h45
  text ".PRJ_Customer" at 11393.5,-163.5 h70
  text "D" at -416.5,-231.5 h70
  text "D" at 14383.5,-231.5 h70
  text "FILE NAME:" at 11343.5,-323.5 h45
  text ".PCB_File_Name_No_Path" at 11393.5,-443.5 h70
  text "Texas Instruments (TI) and/or its licensors do not warrant the accuracy or completeness of this specification" at 6374,-605.34 h45
  text "ENGINEER:" at 11343.5,-613.5 h45
  text "LAYOUT BY:" at 12848.5,-613.5 h45
  text "or any information contained therein. TI and/or its licensors do not warrant that this design will meet" at 6329.01,-718 h45
  text ".PRJ_Engineer" at 11393.5,-768.49 h70
  text ".PCB_Layout" at 12899,-768.49 h70
  text "the specifications, will be suitable for your application or fit for any particular purpose, or will operate in" at 6329.01,-830.67 h45
  text ".Layer_Name" at 577,-858.49 h60
  text "ALTIUM DESIGNER VERSION:" at 12848.5,-923.5 h45
  text "an implementation. TI and/or its licensors do not warrant that the design is production worthy. You should" at 6329.01,-943.33 h45
  text "completely validate and test your design implementation to confirm the system functionality for your application." at 6374,-1056 h45
  text ".print_Scale" at 11393.5,-1056.83 h70
  text ".Application_BuildNumber" at 12899,-1056.83 h70
  text "1" at 739.84,-1263.5 h70
  text "2" at 3235.5,-1263.5 h70
  text "3" at 5724.84,-1263.5 h70
  text "4" at 8231.51,-1263.5 h70
  text "5" at 10730.5,-1263.5 h70
  text "6" at 13235.5,-1263.5 h70
M10 Fab Notes:
  drawing of 173 lines, arcs and shapes, not listed
  text "DESIGN INFORMATION" at 12378.02,6201 h60
  text "MIN. TRACK WIDTH:" at 11733.46,6021 h60
  text "8" at 12829.7,6021 h60
  text "MIL" at 12984.46,6021 h60
  text "MIN. CLEARANCE:" at 11733.46,5889 h60
  text "0.2" at 12769.7,5889 h60
  text "mm" at 12984.46,5889 h60
  text "MIN. VIA PAD SIZE:" at 11733.46,5757 h60
  text "24" at 12799.71,5757 h60
  text "MIL" at 12984.46,5757 h60
  text "0.05mm (2MIL)" at 12428.46,5615.29 h60
  text "MINIMUM ANNULAR RING" at 11404.23,5611 h60
  text "EXTERNAL" at 13136.46,5611 h60
  text "PER" at 11604.23,5493 h60
  text "IPC-D-275 CLASS 2 LEVEL C" at 11824.23,5493 h60
  text "MIL, HOLES" at 13312.46,5380.71 h60
  text "+/-" at 12920,5380 h60
  text "+/-" at 13774,5380 h60
  text "REGISTRATION TOLERANCES:" at 11404.23,5375 h60
  text "METAL" at 12604,5375 h60
  text "5" at 13180.2,5375 h60
  text "3" at 14013.2,5375 h60
  text "MIL" at 14129.46,5375 h60
  text "+/-" at 13774,5262 h60
  text "HOLE SIZE TOLERANCE (UNLESS OTHERWISE SPECIFIED):" at 11404.23,5257 h60
  text "3" at 14013.2,5257 h60
  text "MIL" at 14129.46,5257 h60
  text "MATERIAL:" at 11329.46,5047.54 h60
  text "FR-4 High Tg" at 12315.9,4907.21 h60
  text "FR-408" at 11750.46,4898.64 h60
  text "OTHER" at 13238.46,4898.64 h60
  text "X" at 12161,4895 h60
  text "62 MIL (1.6mm) +/-10%" at 12070.56,4735.92 h60
  text "THICKNESS:" at 11404.23,4731.64 h60
  text "X" at 11942.4,4731.64 h60
  text "OTHER" at 13355.46,4731.64 h60
  text "TOLERANCE:" at 11404.23,4573.64 h60
  text "X" at 12243.53,4573.64 h60
  text "ANSI IPC-6012 TYPE 3 CLASS 2" at 12430.48,4573.64 h60
  text "OTHER +/-" at 12430.46,4417.64 h60
  text "BOW & TWIST:" at 11404.23,4260.64 h60
  text "X" at 12243.53,4260.64 h60
  text "ANSI IPC-6012 TYPE 3 CLASS 2" at 12430.48,4260.64 h60
  text "OTHER +/-" at 12430.46,4102.13 h60
  text "DRILLING:" at 11329.46,3963.64 h60
  text "REFERENCE:" at 11404.23,3846.64 h60
  text "X" at 12052.46,3846.64 h60
  text "AS SHOWN" at 12239.46,3846.64 h60
  text "X" at 12953.46,3846.64 h60
  text "NC_DRILL FILES" at 13090.46,3846.64 h60
  text "PTH COPPER THICKNESS:" at 11404.23,3688.64 h60
  text "X" at 12534.46,3688.64 h60
  text "20-30 um" at 12671.46,3688.64 h60
  text "OTHER" at 13388.46,3688.64 h60
  text "BOARD FINISH:" at 11329.46,3529.64 h60
  text "SILKSCREEN:" at 11484.68,3411.64 h60
  text "X" at 12433.46,3411.64 h60
  text "TOP" at 12559.46,3411.64 h60
  text "X" at 12943.46,3411.64 h60
  text "BOTTOM" at 13070.46,3411.64 h60
  text "SILKSCREEN COLOR:" at 11484.68,3244.64 h60
  text "X" at 12432.42,3244.64 h60
  text "WHITE" at 12559.46,3244.64 h60
  text "OTHER" at 13070.46,3244.64 h60
  text "X" at 12563.42,3085.44 h60
  text "GREEN" at 12690.46,3085.44 h60
  text "OTHER" at 13308.46,3085.44 h60
  text "SOLDER RESIST COLOR:" at 11484.68,3074.64 h60
  text "X" at 12563.42,2915.44 h60
  text "MATTE" at 12690.46,2915.44 h60
  text "SEMI-GLOSS" at 13308,2914.8 h60
  text "IMMERSION GOLD (ENIG)" at 12390.46,2726.92 h60
  text "ENEPIG" at 13728,2723.64 h60
  text "SURFACE FINISH:" at 11329.46,2722.64 h60
  text "X" at 12203.51,2722.64 h60
  text "IMM. TIN/SILVER OR EQUIV" at 11659,2565.64 h60
  text "OTHER" at 13090.46,2565.64 h60
  text "ARRAY/PANEL:" at 11329.46,2386.64 h60
  text "CUT AND TRIM PER M1 BOARD OUTLINE" at 12390.46,2382.35 h60
  text "N.C. ROUTE" at 12390.46,2230.64 h60
  text "X" at 13069.46,2230.64 h60
  text "V. SCORE" at 13256.46,2230.64 h60
  text "CERTIFICATION:" at 11329.46,2093.64 h60
  text "MATERIALS AND WORKMANSHIP FOR ALL PCBS" at 12054.46,2093.64 h60
  text "TO MEET OR EXCEED THE REQUIREMENTS OF:" at 12054.46,1995.64 h60
  text "X" at 11680.96,1859.13 h60
  text "ANSI IPC-A-600F CLASS ->" at 11819.96,1859.13 h60
  text "X" at 13459.02,1859.13 h60
  text "2" at 13577.96,1859.14 h60
  text "1" at 13262.96,1857.64 h60
  text "3" at 13931.96,1857.64 h60
  text "X" at 12495.02,1699.64 h60
  text "RoHS" at 12631.96,1699.64 h60
  text "OTHER" at 13276.36,1699.64 h60
  text "PER ORDER" at 13673.42,1699.64 h60
  text "ALL BOARDS MUST MEET OR EXCEED UL94-V0 REQUIREMENTS." at 11357,1534 h60
  text "PCB MUST BEAR THE UL94V-0 UL REGISTERED MATERIAL ID NUMBER" at 11357,1414 h60
  text "ADDITIONAL REQUIREMENTS:" at 11329.46,1240.64 h60
  text "MICROSECTION:" at 11404.23,1125.64 h60
  text "YES" at 12309.96,1125.64 h60
  text "REQUIRED" at 13171.46,969.49 h60
  text "BARE BOARD ELEC. TEST:" at 11404.23,966.64 h60
  text "NONE" at 12709.96,966.64 h60
  text "X" at 13044.46,966.64 h60
  text "PER ORDER" at 13763.46,966.64 h60
  text ".Layer_Name" at 577,-858.49 h60
M11 Gerber Information:
  lines w10: -292,-930.17 6308,-930.17 ; -292,-726.83 6310,-726.83 ; -292,-523.5 -292,-1133.5 3713,-1133.5 6310,-1133.5 6310,-523.5 -291.5,-523.5 -291.5,-1133.5 1284,-1133.5 ; 2173,-1133.5 2173,-523.5 ; 3440,-726.83 3440,-523.5 ; 4280,-726.83 4280,-523.5 ; 4902,-1140 4902,-937.17
  text "ALL ARTWORK VIEWED FROM TOP SIDE" at -228.5,-655.67 h60
  text "BOARD #:" at 2248,-655.67 h60
  text ".PRJ_Number" at 2793.5,-655.67 h60
  text "REV:" at 3638,-655.67 h60
  text ".PCB_Rev" at 3929.5,-655.67 h60
  text "SVN REV:" at 4476,-655.67 h60
  text ".VersionControl_RevNumber" at 4982,-655.67 h60
  text "LAYER NAME =" at -228.5,-858.49 h60
  text "TID #:" at 2248,-859 h60
  text ".TID" at 2793.5,-859 h60
  text "PLOT NAME =" at -228.5,-1064.34 h60
  text ".plot_File_Name" at 577,-1064.34 h60
  text "GENERATED    :" at 2250,-1064.34 h60
  text ".Print_Date" at 3119.5,-1064.34 h60
  text ".Print_Time" at 3848.5,-1064.34 h60
  text "TEXAS INSTRUMENTS" at 5113,-1064.34 h60
M12 Stackup:
  drawing of 191 lines, arcs and shapes, not listed
  text "Layer" at 9790.34,7830 h60
  text "Name" at 10200.26,7830 h60
  text "Material" at 11130,7830 h60
  text "Thickness" at 11989.77,7830 h60
  text "Constant" at 12639.6,7830 h60
  text "Board Layer Stack" at 13209.46,7830 h60
  text "1" at 9790.34,7710 h60
  text "Top Overlay" at 10200.26,7710 h60
  text "2" at 9790.34,7590 h60
  text "Top Solder" at 10200.26,7590 h60
  text "Solder Resist" at 11130,7590 h60
  text "0.40mil" at 11989.77,7590 h60
  text "3.5" at 12639.6,7590 h60
  text "3" at 9790.34,7470 h60
  text "Top Layer" at 10200.26,7470 h60
  text "Copper" at 11130,7470 h60
  text "1.40mil" at 11989.77,7470 h60
  text "4" at 9790.34,7350 h60
  text "Dielectric1" at 10200.26,7350 h60
  text "FR-4" at 11130,7350 h60
  text "59.20mil" at 11989.77,7350 h60
  text "4.8" at 12639.6,7350 h60
  text "5" at 9790.34,7230 h60
  text "Bottom Layer" at 10200.26,7230 h60
  text "Copper" at 11130,7230 h60
  text "1.40mil" at 11989.77,7230 h60
  text "6" at 9790.34,7110 h60
  text "Bottom Solder" at 10200.26,7110 h60
  text "Solder Resist" at 11130,7110 h60
  text "0.40mil" at 11989.77,7110 h60
  text "3.5" at 12639.6,7110 h60
  text "7" at 9790.34,6990 h60
  text "Bottom Overlay" at 10200.26,6990 h60
  text ".Layer_Name" at 577,-858.49 h60
M13 Component Bodies Top:
  text ".Layer_Name" at 577,-858.49 h60
M14 Component Bodies Bottom:
  text ".Layer_Name" at 577,-858.49 h60
M15 Courtyards Top:
  text ".Layer_Name" at 577,-858.49 h60
M16 Courtyards Bottom:
  text ".Layer_Name" at 577,-858.49 h60
Drill Drawing:
  circle w10: c5348.9,3003.9 r22.14
  circle w10: c5348.9,2505.78 r13.28
  circle w10: c5348.9,2505.78 r22.14
  lines w10: 5326.76,2594.33 5337.83,2594.33 5348.9,2583.26 5359.97,2594.33 5371.04,2594.33 5359.97,2605.4 5371.04,2616.47 5359.97,2616.47 5348.9,2627.54 5337.83,2616.47 5326.76,2616.47 5337.83,2605.4 5326.76,2594.33 ; 5326.76,2682.89 5371.04,2682.89 5371.04,2727.17 5326.76,2727.17 5326.76,2682.89 ; 5326.76,2826.79 5371.04,2826.79 5348.9,2782.51 5326.76,2826.79 ; 5326.76,2904.28 5348.9,2882.14 5371.04,2904.28 5348.9,2926.42 5326.76,2904.28 ; 5326.76,3081.39 5326.76,3092.46 5337.83,3103.53 5326.76,3114.6 5326.76,3125.67 5337.83,3125.67 5348.9,3114.6 5359.97,3125.67 5371.04,3125.67 5371.04,3114.6 5359.97,3103.53 5371.04,3092.46 5371.04,3081.39 5359.97,3081.39 5348.9,3092.46 5337.83,3081.39 5326.76,3081.39 ; 5326.76,3192.08 5337.83,3192.08 5348.9,3181.01 5359.97,3192.08 5371.04,3192.08 5359.97,3203.15 5371.04,3214.22 5359.97,3214.22 5348.9,3225.29 5337.83,3214.22 5326.76,3214.22 5337.83,3203.15 5326.76,3192.08 ; 5326.76,3280.64 5348.9,3291.71 5371.04,3280.64 5359.97,3302.78 5371.04,3324.92 5348.9,3313.85 5326.76,3324.92 5337.83,3302.78 5326.76,3280.64 ; 5335.62,3196.51 5342.26,3196.51 5348.9,3189.87 5355.54,3196.51 5362.18,3196.51 5355.54,3203.15 5362.18,3209.79 5355.54,3209.79 5348.9,3216.43 5342.26,3209.79 5335.62,3209.79 5342.26,3203.15 5335.62,3196.51
  lines w12: 5286,2453.75 8398.79,2453.75 ; 5286,3350.38 8398.79,3350.38 ; 5601.62,2354.12 5601.62,3450 ; 5918.86,2354.12 5918.86,3450 ; 6540.41,2354.12 6540.41,3450 ; 6784.69,2354.12 6784.69,3450 ; 7145,2354.12 7145,3450 ; 7854.63,2354.12 7854.63,3450 ; 5286,2354.12 8398.79,2354.12 8398.79,3450 5286,3450 5286,2354.12
  text "Symbol" at 5345.77,3380.26 h72
  text "Quantity" at 5631.51,3380.26 h72
  text "Finished Hole Size" at 5948.74,3380.26 h72
  text "Plated" at 6570.3,3380.26 h72
  text "Hole Type" at 6814.57,3380.26 h72
  text "Drill Layer Pair" at 7174.89,3380.26 h72
  text "Hole Tolerance" at 7884.51,3380.26 h72
  text "146" at 5631.51,3280.64 h60
  text "7.87mil (0.200mm)" at 5948.74,3280.64 h60
  text "PTH" at 6570.3,3280.64 h60
  text "Round" at 6814.57,3280.64 h60
  text "Top Layer - Bottom Layer" at 7174.89,3280.64 h60
  text "214" at 5631.51,3181.01 h60
  text "10.00mil (0.254mm)" at 5948.74,3181.01 h60
  text "PTH" at 6570.3,3181.01 h60
  text "Round" at 6814.57,3181.01 h60
  text "Top Layer - Bottom Layer" at 7174.89,3181.01 h60
  text "5" at 5631.51,3081.39 h60
  text "33.46mil (0.850mm)" at 5948.74,3081.39 h60
  text "PTH" at 6570.3,3081.39 h60
  text "Round" at 6814.57,3081.39 h60
  text "Top Layer - Bottom Layer" at 7174.89,3081.39 h60
  text "4" at 5631.51,2981.76 h60
  text "35.43mil (0.900mm)" at 5948.74,2981.76 h60
  text "PTH" at 6570.3,2981.76 h60
  text "Round" at 6814.57,2981.76 h60
  text "Top Layer - Bottom Layer" at 7174.89,2981.76 h60
  text "8" at 5631.51,2882.14 h60
  text "39.37mil (1.000mm)" at 5948.74,2882.14 h60
  text "PTH" at 6570.3,2882.14 h60
  text "Round" at 6814.57,2882.14 h60
  text "Top Layer - Bottom Layer" at 7174.89,2882.14 h60
  text "9" at 5631.51,2782.51 h60
  text "40.00mil (1.016mm)" at 5948.74,2782.51 h60
  text "PTH" at 6570.3,2782.51 h60
  text "Round" at 6814.57,2782.51 h60
  text "Top Layer - Bottom Layer" at 7174.89,2782.51 h60
  text "20" at 5631.51,2682.89 h60
  text "40.94mil (1.040mm)" at 5948.74,2682.89 h60
  text "PTH" at 6570.3,2682.89 h60
  text "Round" at 6814.57,2682.89 h60
  text "Top Layer - Bottom Layer" at 7174.89,2682.89 h60
  text "2" at 5631.51,2583.26 h60
  text "55.12mil (1.400mm)" at 5948.74,2583.26 h60
  text "PTH" at 6570.3,2583.26 h60
  text "Round" at 6814.57,2583.26 h60
  text "Top Layer - Bottom Layer" at 7174.89,2583.26 h60
  text "2" at 5631.51,2483.64 h60
  text "125.98mil (3.200mm)" at 5948.74,2483.64 h60
  text "PTH" at 6570.3,2483.64 h60
  text "Round" at 6814.57,2483.64 h60
  text "Top Layer - Bottom Layer" at 7174.89,2483.64 h60
  text "410 Total" at 5631.51,2384.01 h60
  text ".Layer_Name" at 577,-858.49 h60
M17 Embedded Cavity:
  text ".Layer_Name" at 577,-858.49 h60
M18 Embedded Assembly:
  text ".Layer_Name" at 577,-858.49 h60
M19 Embedded Keepout:
  text ".Layer_Name" at 577,-858.49 h60

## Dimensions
0,0 to 0,5250 on M2 Board Dimensions
0,-400 to 1000,-400 on M2 Board Dimensions
3000,0 to 0,5250 on M2 Board Dimensions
